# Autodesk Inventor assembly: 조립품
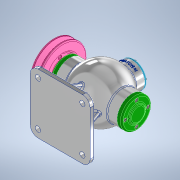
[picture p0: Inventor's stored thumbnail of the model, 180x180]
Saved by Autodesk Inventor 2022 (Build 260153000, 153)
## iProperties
Created: 2024-04
Part Number: 조립품
Document SubType Name: Assembly
Designer: Admin
Author: Admin
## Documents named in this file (15)
- C:\Users\Admin\Desktop\760406V1018\조립품.iam
- C:\Users\Admin\Desktop\760406V1018\본체.ipt
- C:\Users\Admin\Desktop\760406V1018\뒤커버.ipt
- C:\Users\Admin\Desktop\760406V1018\앞커버.ipt
- C:\Users\Admin\Desktop\760406V1018\오일실 15 30 7.ipt
- C:\Users\Admin\Desktop\760406V1018\베어링- 6202.ipt
- KS B 2023 - 6202 - 15 x 35 x 11 - 7.8.ipt
- C:\Users\Admin\Desktop\760406V1018\칼라.ipt
- C:\Users\Admin\Desktop\760406V1018\편심축.ipt
- C:\Users\Admin\Desktop\760406V1018\키 4 x 4 x 12.ipt
- C:\Users\Admin\Desktop\760406V1018\볼트 M4 x 16.ipt
- C:\Users\Admin\Desktop\760406V1018\V-벨트풀리.ipt
- C:\Users\Admin\Desktop\760406V1018\너트 M8.ipt
- C:\Users\Admin\Desktop\760406V1018\상부커버.ipt
- C:\Users\Admin\Desktop\760406V1018\볼트 M4 x 12.ipt
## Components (15 placed, 4 different names)
1. KS B 2023 - 6202 - 15 x 35 x 11 - 7.8:1
2. KS B 2023 - 6202 - 15 x 35 x 11 - 7.8:2
3. ISO 4762 M4 x 16:1
4. ISO 4762 M4 x 16:2
5. ISO 4762 M4 x 16:3
6. ISO 4762 M4 x 16:4
7. ISO 4762 M4 x 16:5
8. ISO 4762 M4 x 16:6
9. ISO 4762 M4 x 16:7
10. ISO 4762 M4 x 16:8
11. V-벨트풀리:1
12. KS B 1021 - 에 따름 ISO 1207 - 미터 A  M 4 x 12:1
13. KS B 1021 - 에 따름 ISO 1207 - 미터 A  M 4 x 12:2
14. KS B 1021 - 에 따름 ISO 1207 - 미터 A  M 4 x 12:3
15. KS B 1021 - 에 따름 ISO 1207 - 미터 A  M 4 x 12:4
